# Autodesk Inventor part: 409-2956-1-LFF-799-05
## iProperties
Created: 2010-11
Part Number: 409-2956-1-LFF-799-05
Material: 3/4" OD TUBE - SS
Document SubType Name: Modeling
Designer: S. Boerckel
Engineer: Steve Boerckel
Mass: 726.443 g
Surface Area: 1090.92 cm^2
Volume: 89.9063 cm^3
Density: 8.08 g/cm^3
Description: DRAIN TUBING
LGTH: 39.223 in
Author: S. Boerckel
Revision Number: 0
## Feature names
1. TaggingFeature1
